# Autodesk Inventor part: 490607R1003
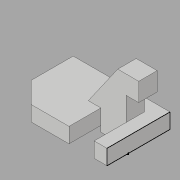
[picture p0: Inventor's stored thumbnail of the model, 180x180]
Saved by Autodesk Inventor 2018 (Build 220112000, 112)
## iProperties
Created: 2019-06
Part Number: 490607R1003
Material: 일반
Document SubType Name: Modeling
Designer: 6507_13
Density: 1 g/cm^3
Appearance: 기본값
Author: 6507_13
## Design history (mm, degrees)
sketch "스케치1"
  geometry: L1 (-25, 25)-(-70, 25); L2 (-70, 25)-(-70, -13); L3 (-70, -13)-(-100, -13); L4 (-100, -13)-(-100, 25); L5 (-100, 25)-(-115, 25); L6 (-115, 25)-(-115, -50); L7 (-115, -50)-(-70, -50); L8 (-70, -50)-(0, -50); L9 (-25, 25)-(0, 0); L10 (0, 0)-(0, -50); 1 further point
  constraints: 20 end point, 4 perpendicular, 4 point on line, 1 coincident, 1 horizontal, 1 vertical
  dimensions: "d0" = 45 distance of L1.start L1.end; "d1" = 38 distance of L1.end L2.end; "d2" = 30 distance of L2.end L3.end; "d3" = 15 distance of L4.end L5.end; "d4" = 75 distance of L5.end L6.end; "d5" = 45 distance of L6.end L7.end; "d6" = 70 distance of L7.end L8.end; "d7" = 45 deg angle of L9 L1
extrude "돌출1" new body sketch "스케치1" distance "d8" = 18; taper "d9" = 0 deg
sketch "스케치2"
  geometry: L1 (0, 0)-(30, 0) reference; L2 (30, 0)-(30, 18) reference; L3 (0, 18)-(30, 18) reference; L4 (0, 0)-(0, 18) reference; L5 (0, 0)-(0, -7); L6 (0, -7)-(30, -7); L7 (30, -7)-(30, 0); L8 (30, 46)-(45, 46); L9 (30, 46)-(30, 18); L10 (45, 46)-(45, 68); L11 (45, 68)-(20, 68); L12 (20, 68)-(-22.343, 7.528); L13 (0, 18)-(-15.01, 18); 1 further point
  constraints: 18 end point, 3 perpendicular, 3 vertical, 2 horizontal, 2 point on line
  dimensions: "d10" = 7 distance of L1.start L5.end; "d11" = 25 distance of L10.end L11.end; "d12" = 55 deg angle of L12 L11; "d13" = 15 distance of L8.start L8.end; "d14" = 75 vertical distance of L6.end L10.end; "d15" = 22 distance of L8.end L10.end
extrude "돌출2" join sketch "스케치2" distance "d16" = 22; taper "d17" = 0 deg
sketch "스케치3"
  geometry: L1 (0, 0)-(75, 0) reference; L2 (75, 0)-(75, 18) reference; L3 (0, 18)-(75, 18) reference; L4 (0, 0)-(0, 18) reference; 1 further point
node "솔리드1"
